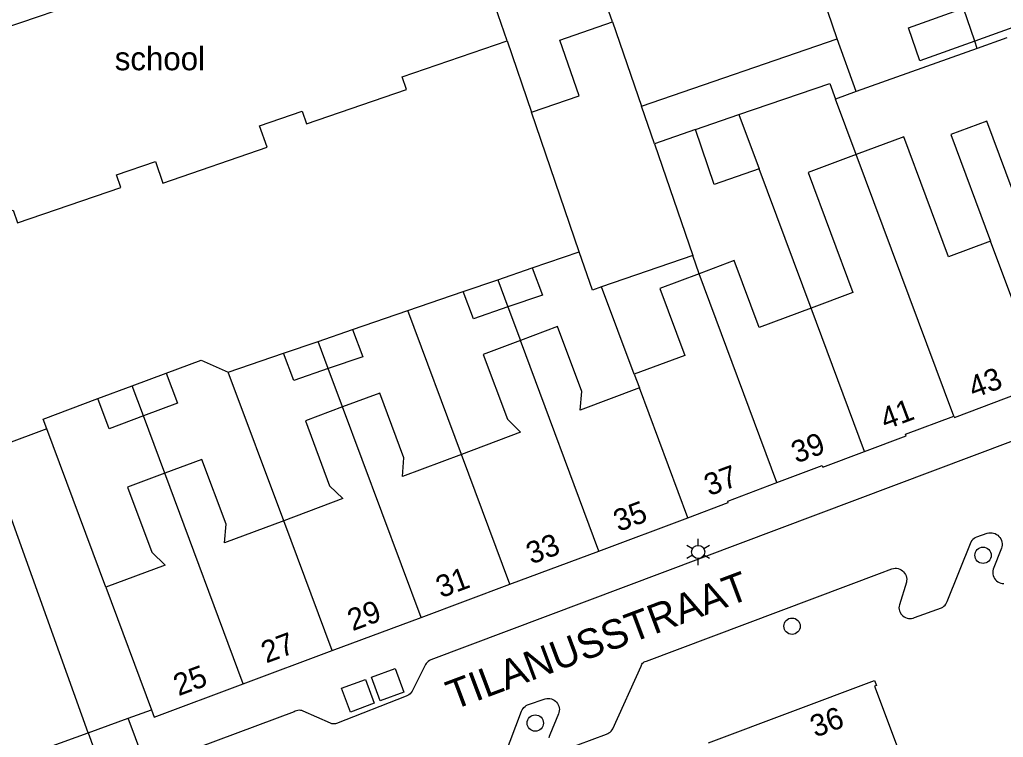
# Model space of a CAD drawing. Extents: x 122462 to 123306, y 485548 to 486417.
# Drawn here: x 122566.2 to 122633.7, y 485724 to 485773.2 of the extents above; entities that cross this region are included whole.
import ezdxf

# ---------------------------------------------------------------- set-up
doc = ezdxf.new("R2010")
doc.units = 0
for name, color, linetype in [('Level 1', 7, 'Continuous'), ('Level 17', 7, 'Continuous'), ('Level 19', 7, 'Continuous'), ('Level 2', 7, 'Continuous'), ('Level 23', 7, 'Continuous'), ('Level 4', 7, 'Continuous'), ('Level 42', 7, 'Continuous'), ('Level 50', 7, 'Continuous'), ('Level 53', 7, 'Continuous'), ('Level 58', 7, 'Continuous'), ('Level 59', 7, 'Continuous'), ('Level 62', 7, 'Continuous')]:
    doc.layers.add(name, color=color, linetype=linetype)

msp = doc.modelspace()

# ---------------------------------------------------------------- linework, layer by layer
at = {"layer": 'Level 1'}
for p, q in [((122622.308, 485771.864), (122619.273, 485780.677)), ((122606.89, 485773.012), (122608.877, 485767.241)), ((122599.667, 485771.71), (122601.342, 485766.825)), ((122608.877, 485767.241), (122622.308, 485771.864)), ((122608.389, 485748.86), (122608.738, 485747.923)), ((122570.939, 485724.289), (122563.647, 485744.62)), ((122605.964, 485736.746), (122612.059, 485739.019)), ((122599.868, 485734.471), (122605.964, 485736.746)), ((122593.771, 485732.196), (122599.868, 485734.471)), ((122572.16, 485734.272), (122575.296, 485725.867)), ((122587.674, 485729.921), (122593.771, 485732.196)), ((122581.578, 485727.646), (122587.674, 485729.921))]:
    msp.add_line(p, q, dxfattribs=at)
for points in [[(122595.705, 485783.261), (122588.35, 485780.749), (122588.42, 485780.539), (122577.601, 485776.821), (122577.531, 485777.031), (122573.371, 485775.601), (122573.443, 485775.393), (122562.65, 485771.719), (122562.57, 485771.939), (122555.33, 485769.42), (122555.347, 485769.372), (122554.835, 485769.176)], [(122601.342, 485766.825), (122604.6, 485767.946), (122603.283, 485771.77), (122606.89, 485773.012)], [(122558.935, 485757.75), (122565.807, 485760.105), (122566.103, 485759.241), (122573.182, 485761.667), (122572.886, 485762.531), (122575.552, 485763.445), (122576.058, 485761.968), (122583.208, 485764.419), (122582.702, 485765.895), (122585.619, 485766.895), (122585.915, 485766.032), (122592.763, 485768.378), (122592.467, 485769.242), (122599.667, 485771.71)], [(122637.375, 485762.692), (122634.303, 485761.544), (122632.561, 485766.211), (122630.086, 485765.287), (122632.813, 485757.981)], [(122632.813, 485757.981), (122629.938, 485756.907), (122626.862, 485765.144), (122623.606, 485763.929)], [(122623.606, 485763.929), (122620.305, 485762.696), (122623.381, 485754.458), (122620.52, 485753.389)], [(122620.52, 485753.389), (122616.957, 485752.059), (122615.244, 485756.65), (122612.832, 485755.75)], [(122612.832, 485755.75), (122610.147, 485754.748), (122611.861, 485750.156), (122608.389, 485748.86)], [(122608.738, 485747.923), (122604.685, 485746.411), (122604.788, 485747.677), (122603.127, 485752.127), (122600.577, 485751.176)], [(122600.577, 485751.176), (122598.029, 485750.225), (122599.691, 485745.775), (122600.599, 485744.886), (122596.544, 485743.373)], [(122630.304, 485745.99), (122630.34, 485745.89), (122636.459, 485748.209)], [(122596.544, 485743.373), (122592.493, 485741.861), (122592.596, 485743.127), (122590.935, 485747.577), (122588.386, 485746.626)], [(122588.386, 485746.626), (122585.838, 485745.675), (122587.499, 485741.225), (122588.407, 485740.336), (122584.352, 485738.823)], [(122624.183, 485743.579), (122627.029, 485744.65), (122626.993, 485744.754), (122630.304, 485745.99)], [(122618.173, 485741.437), (122621.283, 485742.602), (122621.32, 485742.499), (122624.183, 485743.579)], [(122584.352, 485738.823), (122580.3, 485737.311), (122580.403, 485738.577), (122578.742, 485743.027), (122576.194, 485742.075)], [(122576.194, 485742.075), (122573.645, 485741.124), (122575.306, 485736.674), (122576.214, 485735.785), (122572.16, 485734.272)], [(122612.059, 485739.019), (122614.83, 485740.069), (122614.793, 485740.172), (122618.173, 485741.437)], [(122613.479, 485723.61), (122624.865, 485727.866), (122624.992, 485727.527), (122624.861, 485727.478), (122628.175, 485718.665), (122628.268, 485718.701), (122628.344, 485718.508)], [(122575.296, 485725.867), (122575.479, 485725.37), (122581.578, 485727.646)], [(122545.965, 485718.624), (122563.597, 485724.974), (122564.658, 485722.028), (122570.939, 485724.289)]]:
    msp.add_lwpolyline(points, dxfattribs=at)
at = {"layer": 'Level 17'}
for points in [[(122655.401, 485752.212), (122594.436, 485729.289), (122594.347, 485729.242), (122594.265, 485729.184), (122594.189, 485729.117), (122594.123, 485729.041), (122594.066, 485728.958), (122593.149, 485727.13), (122593.09, 485727.041), (122593.019, 485726.961), (122592.938, 485726.893), (122592.847, 485726.837), (122592.749, 485726.795), (122587.983, 485724.929), (122587.899, 485724.908), (122587.813, 485724.898), (122587.727, 485724.899), (122587.641, 485724.912), (122587.558, 485724.937), (122585.692, 485725.779), (122585.604, 485725.808), (122585.513, 485725.826), (122585.42, 485725.831), (122585.327, 485725.823), (122585.236, 485725.803), (122585.149, 485725.771), (122585.067, 485725.728), (122578.503, 485723.286)], [(122603.544, 485723.1), (122606.476, 485724.192), (122606.566, 485724.231), (122606.651, 485724.28), (122606.73, 485724.339), (122606.801, 485724.407), (122606.863, 485724.483), (122606.916, 485724.566), (122608.853, 485728.854), (122608.877, 485728.926), (122608.912, 485728.992), (122608.958, 485729.053), (122609.013, 485729.104), (122609.075, 485729.146), (122609.144, 485729.178), (122609.217, 485729.197), (122625.209, 485735.197), (122626.049, 485735.529), (122626.156, 485735.556), (122626.266, 485735.567), (122626.376, 485735.563), (122626.484, 485735.543), (122626.589, 485735.508), (122626.688, 485735.459), (122626.778, 485735.396), (122626.859, 485735.321), (122626.928, 485735.235), (122626.985, 485735.14), (122627.027, 485735.038), (122627.055, 485734.931), (122627.067, 485734.822), (122627.064, 485734.712), (122627.045, 485734.603), (122626.565, 485733.065), (122626.545, 485732.96), (122626.54, 485732.854), (122626.551, 485732.748), (122626.575, 485732.644), (122626.615, 485732.545), (122626.668, 485732.453), (122626.733, 485732.369), (122626.809, 485732.295), (122626.895, 485732.232), (122626.989, 485732.182), (122627.089, 485732.146), (122627.194, 485732.124), (122627.3, 485732.117), (122627.406, 485732.125), (122627.51, 485732.148), (122627.61, 485732.185), (122629.451, 485732.853), (122629.54, 485732.899), (122629.622, 485732.957), (122629.695, 485733.026), (122629.756, 485733.105), (122629.806, 485733.192), (122629.842, 485733.286), (122631.498, 485737.379), (122631.549, 485737.469), (122631.612, 485737.551), (122631.688, 485737.622), (122631.773, 485737.681), (122631.866, 485737.726), (122632.593, 485737.973), (122632.7, 485737.996), (122632.809, 485738.004), (122632.918, 485737.997), (122633.026, 485737.975), (122633.129, 485737.939), (122633.226, 485737.889), (122633.316, 485737.825), (122633.395, 485737.751), (122633.464, 485737.665), (122633.521, 485737.572), (122633.564, 485737.471), (122633.592, 485737.365), (122633.606, 485737.257), (122633.605, 485737.147), (122633.589, 485737.039), (122633.558, 485736.934), (122633.008, 485735.495), (122632.983, 485735.389), (122632.974, 485735.281), (122632.981, 485735.172), (122633.003, 485735.066), (122633.04, 485734.963), (122633.091, 485734.867), (122633.156, 485734.78), (122633.233, 485734.703), (122633.319, 485734.637), (122633.415, 485734.585), (122633.517, 485734.547), (122633.623, 485734.523), (122633.731, 485734.516)], [(122599.107, 485721.669), (122600.664, 485725.777), (122600.707, 485725.868), (122600.762, 485725.953), (122600.828, 485726.03), (122600.903, 485726.097), (122600.987, 485726.154), (122601.077, 485726.199), (122602.281, 485726.615), (122602.386, 485726.638), (122602.493, 485726.645), (122602.599, 485726.638), (122602.704, 485726.615), (122602.805, 485726.579), (122602.899, 485726.528), (122602.985, 485726.464), (122603.062, 485726.389), (122603.127, 485726.304), (122603.179, 485726.211), (122603.218, 485726.111), (122603.243, 485726.007), (122603.252, 485725.9), (122603.247, 485725.793), (122603.226, 485725.688), (122603.191, 485725.587), (122602.589, 485724.147), (122602.554, 485724.042), (122602.533, 485723.933)], [(122575.126, 485721.434), (122573.696, 485725.288)], [(122570.939, 485724.289), (122572.307, 485720.5)]]:
    msp.add_lwpolyline(points, dxfattribs=at)
at = {"layer": 'Level 19'}
for p, q in [((122623.605, 485768.235), (122622.308, 485771.864)), ((122631.898, 485771.2), (122631.731, 485771.69)), ((122633.925, 485771.925), (122631.898, 485771.2)), ((122631.898, 485771.2), (122623.605, 485768.235)), ((122623.605, 485768.235), (122622.187, 485767.728)), ((122623.606, 485763.929), (122622.187, 485767.728)), ((122604.622, 485757.262), (122601.342, 485766.825)), ((122609.765, 485764.662), (122608.877, 485767.241)), ((122612.582, 485765.632), (122609.765, 485764.662)), ((122609.765, 485764.662), (122612.403, 485756.998)), ((122620.52, 485753.389), (122616.954, 485762.936)), ((122601.389, 485756.154), (122604.622, 485757.262)), ((122612.403, 485756.998), (122606.152, 485754.854)), ((122612.832, 485755.75), (122612.403, 485756.998)), ((122608.389, 485748.86), (122606.152, 485754.854)), ((122592.865, 485753.23), (122596.658, 485754.531)), ((122599.72, 485753.474), (122600.577, 485751.176)), ((122589.075, 485751.93), (122592.865, 485753.23)), ((122596.544, 485743.373), (122592.865, 485753.23)), ((122580.551, 485749.007), (122584.344, 485750.308)), ((122584.352, 485738.823), (122580.551, 485749.007)), ((122588.386, 485746.626), (122587.406, 485749.251)), ((122576.194, 485742.075), (122574.728, 485746.004)), ((122572.16, 485734.272), (122568.113, 485745.115))]:
    msp.add_line(p, q, dxfattribs=at)
for points in [[(122615.564, 485766.659), (122621.787, 485768.801), (122622.187, 485767.728)], [(122606.152, 485754.854), (122605.522, 485754.638), (122604.622, 485757.262)], [(122576.299, 485748.944), (122578.696, 485749.839), (122580.551, 485749.007)], [(122568.113, 485745.115), (122567.859, 485745.795), (122571.614, 485747.196)], [(122568.113, 485745.115), (122565.115, 485743.997), (122563.647, 485744.62)]]:
    msp.add_lwpolyline(points, dxfattribs=at)
at = {"layer": 'Level 2'}
for p, q in [((122631.731, 485771.69), (122630.957, 485773.953)), ((122612.582, 485765.632), (122615.564, 485766.659)), ((122615.564, 485766.659), (122616.954, 485762.936)), ((122599.023, 485755.342), (122601.389, 485756.154)), ((122596.658, 485754.531), (122599.023, 485755.342)), ((122599.023, 485755.342), (122599.72, 485753.474)), ((122586.709, 485751.119), (122589.075, 485751.93)), ((122584.344, 485750.308), (122586.709, 485751.119)), ((122587.406, 485749.251), (122586.709, 485751.119)), ((122573.956, 485748.07), (122576.299, 485748.944)), ((122571.614, 485747.196), (122573.956, 485748.07)), ((122574.728, 485746.004), (122573.956, 485748.07))]:
    msp.add_line(p, q, dxfattribs=at)
for points in [[(122630.957, 485773.953), (122634.725, 485775.3), (122635.498, 485773.037), (122631.731, 485771.69)], [(122631.731, 485771.69), (122627.964, 485770.343), (122627.191, 485772.607), (122630.957, 485773.953)], [(122616.954, 485762.936), (122613.874, 485761.877), (122612.582, 485765.632)], [(122601.389, 485756.154), (122602.086, 485754.286), (122599.72, 485753.474)], [(122599.72, 485753.474), (122597.355, 485752.663), (122596.658, 485754.531)], [(122589.075, 485751.93), (122589.772, 485750.063), (122587.406, 485749.251)], [(122587.406, 485749.251), (122585.041, 485748.44), (122584.344, 485750.308)], [(122576.299, 485748.944), (122577.071, 485746.878), (122574.728, 485746.004)], [(122574.728, 485746.004), (122572.386, 485745.13), (122571.614, 485747.196)]]:
    msp.add_lwpolyline(points, dxfattribs=at)
at = {"layer": 'Level 23'}
for p, q in [((122573.696, 485725.288), (122575.296, 485725.867)), ((122570.939, 485724.289), (122573.696, 485725.288))]:
    msp.add_line(p, q, dxfattribs=at)
at = {"layer": 'Level 4'}
for p, q in [((122606.89, 485773.012), (122602.549, 485785.62)), ((122599.667, 485771.71), (122595.705, 485783.261)), ((122630.304, 485745.99), (122623.606, 485763.929)), ((122636.459, 485748.209), (122632.813, 485757.981)), ((122618.173, 485741.437), (122612.832, 485755.75)), ((122624.183, 485743.579), (122620.52, 485753.389)), ((122605.964, 485736.746), (122600.577, 485751.176)), ((122612.059, 485739.019), (122608.738, 485747.923)), ((122593.771, 485732.196), (122588.386, 485746.626)), ((122599.868, 485734.471), (122596.544, 485743.373)), ((122581.578, 485727.646), (122576.194, 485742.075)), ((122587.674, 485729.921), (122584.352, 485738.823))]:
    msp.add_line(p, q, dxfattribs=at)
at = {"layer": 'Level 42'}
for points in [[(122590.959, 485726.472), (122590.366, 485728.094), (122591.988, 485728.687), (122592.581, 485727.065), (122590.959, 485726.472)], [(122588.924, 485725.709), (122588.323, 485727.339), (122589.953, 485727.94), (122590.554, 485726.31), (122588.924, 485725.709)]]:
    msp.add_lwpolyline(points, dxfattribs=at)
at = {"layer": 'Level 50'}
for p, q in [((122612.384, 485736.908), (122611.994, 485737.133)), ((122612.774, 485737.133), (122612.774, 485737.583)), ((122613.553, 485737.133), (122613.163, 485736.908)), ((122612.384, 485736.458), (122611.994, 485736.233)), ((122613.553, 485736.233), (122613.163, 485736.458)), ((122612.774, 485735.783), (122612.774, 485736.233))]:
    msp.add_line(p, q, dxfattribs=at)
msp.add_circle((122612.774, 485736.683), 0.45, dxfattribs=at)
at = {"layer": 'Level 53'}
for centre in [(122632.3, 485736.452), (122619.206, 485731.595), (122601.602, 485724.957)]:
    msp.add_circle(centre, 0.56, dxfattribs=at)

# ---------------------------------------------------------------- texts
at = {"layer": 'Level 58'}
for s, rotation, p in [('43', 20.46363, (122631.657, 485747.199)), ('41', 20.46363, (122625.612, 485745.04)), ('39', 20.46363, (122619.502, 485742.738)), ('37', 20.46363, (122613.525, 485740.499)), ('35', 20.46363, (122607.309, 485738.048)), ('33', 20.46363, (122601.326, 485735.816)), ('31', 20.46363, (122595.14, 485733.508)), ('29', 20.46363, (122589.074, 485731.244)), ('27', 20.46363, (122583.153, 485729.034)), ('25', 20.46363, (122577.139, 485726.79)), ('36', 20.53223, (122620.801, 485723.946))]:
    msp.add_text(s, height=1.5, rotation=rotation, dxfattribs=at).set_placement(p)
at = {"layer": 'Level 59'}
msp.add_text('TILANUSSTRAAT', height=2, rotation=20.61707, dxfattribs=at).set_placement((122595.984, 485725.836))
at = {"layer": 'Level 62'}
msp.add_text('school', height=1.6, dxfattribs=at).set_placement((122572.771, 485769.7))

doc.saveas('drawing.dxf')
